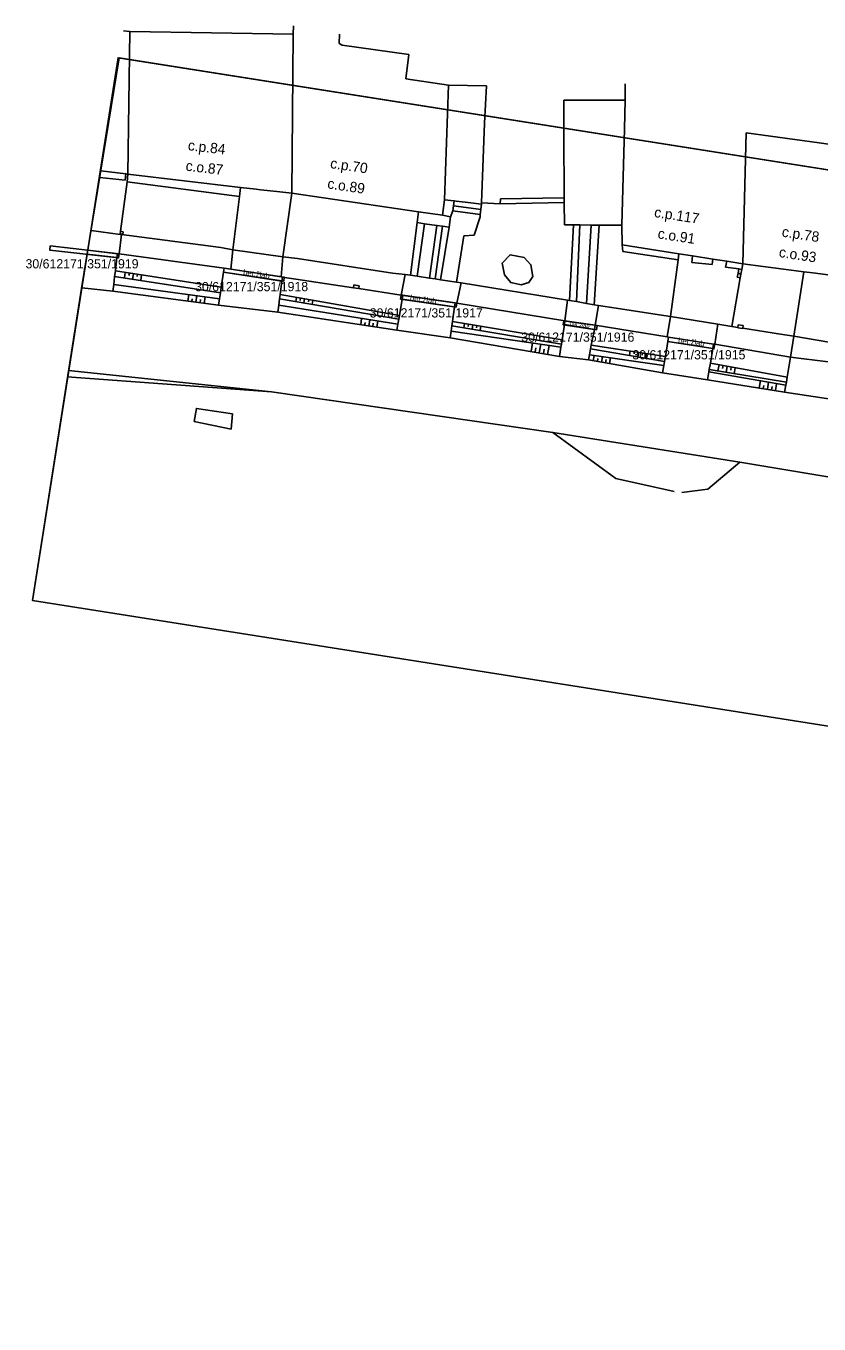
# Model space of a CAD drawing. Extents: x -594451 to -591069, y -1167621 to -1167156.
# Drawn here: x -591409.6 to -591351.9, y -1167315.7 to -1167221.2 of the extents above; entities that cross this region are included whole.
import ezdxf

# ---------------------------------------------------------------- set-up
doc = ezdxf.new("R2010")
doc.units = 0
for name, color, linetype in [('MAPA', 7, 'Continuous'), ('Odvodnění plošné', 7, 'Continuous'), ('Žádosti', 7, 'Continuous')]:
    doc.layers.add(name, color=color, linetype=linetype)

msp = doc.modelspace()

# ---------------------------------------------------------------- linework, layer by layer
at = {"layer": 'MAPA'}
for p, q in [((-591402.511, -1167221.552), (-591402.05, -1167221.59)), ((-591390.15, -1167221.78), (-591390.14, -1167221.19)), ((-591386.774, -1167221.776), (-591386.8, -1167222.46)), ((-591365.975, -1167225.398), (-591365.98, -1167226.59)), ((-591404.241, -1167232.214), (-591402.38, -1167232.41)), ((-591402.75, -1167236.37), (-591404.871, -1167236.093)), ((-591405.15, -1167237.814), (-591402.98, -1167238.05)), ((-591405.103, -1167237.523), (-591402.95, -1167237.77)), ((-591405.545, -1167240.245), (-591403.28, -1167240.5)), ((-591391.73, -1167247.83), (-591406.522, -1167246.268)), ((-591406.6, -1167246.745), (-591391.73, -1167247.83))]:
    msp.add_line(p, q, dxfattribs=at)
for points in [[(-591402.05, -1167221.59), (-591402.18, -1167231.98)], [(-591402.05, -1167221.59), (-591390.15, -1167221.78)], [(-591390.15, -1167221.78), (-591390.25, -1167233.37)], [(-591386.8, -1167222.46), (-591386.58, -1167222.6)], [(-591386.58, -1167222.6), (-591381.73, -1167223.27)], [(-591381.73, -1167223.27), (-591381.96, -1167225.03)], [(-591381.96, -1167225.03), (-591378.85, -1167225.49)], [(-591378.85, -1167225.49), (-591379.14, -1167233.84)], [(-591378.85, -1167225.49), (-591376.08, -1167225.55)], [(-591376.08, -1167225.55), (-591376.228, -1167228.268), (-591376.44, -1167234.06), (-591376.44, -1167234.17)], [(-591370.46, -1167226.6), (-591365.98, -1167226.59)], [(-591370.46, -1167226.6), (-591370.45, -1167229.04), (-591370.43, -1167233.71), (-591370.43, -1167234.05)], [(-591365.98, -1167226.59), (-591366.04, -1167228.67)], [(-591366.04, -1167228.67), (-591366.24, -1167235.69)], [(-591357.18, -1167228.96), (-591357.41, -1167238.5)], [(-591349.29, -1167230.06), (-591351.87, -1167229.7), (-591357.18, -1167228.96)], [(-591404.166, -1167231.75), (-591402.33, -1167231.96), (-591402.18, -1167231.98)], [(-591402.38, -1167232.41), (-591402.33, -1167231.96)], [(-591402.18, -1167231.98), (-591402.25, -1167232.54)], [(-591402.18, -1167231.98), (-591393.99, -1167232.94)], [(-591402.25, -1167232.54), (-591402.72, -1167236.14)], [(-591394.07, -1167233.61), (-591402.25, -1167232.54)], [(-591394.07, -1167233.61), (-591393.99, -1167232.94)], [(-591393.99, -1167232.94), (-591392.85, -1167233.07)], [(-591392.85, -1167233.07), (-591392.53, -1167233.11)], [(-591392.53, -1167233.11), (-591391.35, -1167233.24)], [(-591391.35, -1167233.24), (-591390.25, -1167233.37)], [(-591394.54, -1167237.48), (-591394.07, -1167233.61)], [(-591390.9, -1167237.99), (-591390.25, -1167233.37)], [(-591390.25, -1167233.37), (-591381.02, -1167234.72), (-591379.28, -1167234.97)], [(-591379.14, -1167233.84), (-591379.28, -1167234.97)], [(-591378.28, -1167233.94), (-591378.43, -1167233.92), (-591379.14, -1167233.84)], [(-591378.52, -1167234.66), (-591378.43, -1167233.92)], [(-591378.28, -1167233.94), (-591377.42, -1167234.05)], [(-591376.44, -1167234.17), (-591377.42, -1167234.05)], [(-591376.55, -1167235.08), (-591376.53, -1167234.91), (-591376.44, -1167234.17)], [(-591375.09, -1167234.13), (-591376.44, -1167234.06)], [(-591375.09, -1167234.13), (-591375.06, -1167233.78)], [(-591375.09, -1167234.13), (-591370.43, -1167234.05)], [(-591370.43, -1167233.71), (-591375.06, -1167233.78)], [(-591370.41, -1167235.68), (-591370.43, -1167234.05)], [(-591381.61, -1167239.34), (-591381.14, -1167235.49), (-591381.02, -1167234.72)], [(-591379.42, -1167239.67), (-591378.81, -1167235.83), (-591378.69, -1167235.08)], [(-591378.69, -1167235.08), (-591379.28, -1167234.97)], [(-591378.69, -1167235.08), (-591378.52, -1167234.66)], [(-591378.52, -1167234.66), (-591376.53, -1167234.91)], [(-591378.48, -1167234.29), (-591376.48, -1167234.55)], [(-591376.99, -1167236.43), (-591376.55, -1167235.08)], [(-591402.72, -1167236.14), (-591402.74, -1167236.32)], [(-591402.72, -1167236.14), (-591402.52, -1167236.17)], [(-591381.14, -1167235.49), (-591380.6, -1167235.6)], [(-591381.13, -1167239.41), (-591380.6, -1167235.6), (-591379.69, -1167235.71), (-591380.23, -1167239.55)], [(-591379.81, -1167239.61), (-591379.28, -1167235.77)], [(-591379.69, -1167235.71), (-591379.28, -1167235.77)], [(-591379.28, -1167235.77), (-591378.81, -1167235.83)], [(-591370.41, -1167235.68), (-591369.93, -1167235.68)], [(-591369.74, -1167235.68), (-591370.04, -1167241.17)], [(-591369.93, -1167235.68), (-591369.74, -1167235.68), (-591369.29, -1167235.68), (-591368.47, -1167235.69), (-591367.88, -1167235.69), (-591367.5, -1167235.69)], [(-591369.29, -1167235.68), (-591369.52, -1167241.26)], [(-591368.8, -1167241.39), (-591368.47, -1167235.69)], [(-591367.88, -1167235.69), (-591368.24, -1167241.49)], [(-591367.5, -1167235.69), (-591366.24, -1167235.69)], [(-591366.21, -1167237.13), (-591366.24, -1167235.69)], [(-591402.83, -1167237.78), (-591402.65, -1167236.38)], [(-591402.74, -1167236.32), (-591402.75, -1167236.37)], [(-591395.41, -1167237.33), (-591402.65, -1167236.38), (-591402.75, -1167236.37)], [(-591402.74, -1167236.32), (-591402.56, -1167236.36)], [(-591402.52, -1167236.17), (-591402.56, -1167236.36)], [(-591378.27, -1167239.85), (-591377.72, -1167236.48)], [(-591377.72, -1167236.48), (-591376.99, -1167236.43)], [(-591403.28, -1167240.5), (-591403.22, -1167240.01), (-591403.15, -1167239.43), (-591403.1, -1167239.03), (-591402.98, -1167238.05), (-591402.95, -1167237.77)], [(-591402.95, -1167237.77), (-591402.83, -1167237.78)], [(-591402.83, -1167237.78), (-591395.18, -1167238.83)], [(-591394.54, -1167237.48), (-591395.41, -1167237.33)], [(-591394.54, -1167237.48), (-591394.7, -1167238.9)], [(-591390.9, -1167237.99), (-591394.54, -1167237.48)], [(-591390.9, -1167237.99), (-591391.04, -1167239.45)], [(-591389.85, -1167238.12), (-591390.9, -1167237.99)], [(-591373.34, -1167238.04), (-591372.85, -1167238.58), (-591372.7, -1167239.44), (-591373.01, -1167239.88), (-591373.55, -1167240.04), (-591374.32, -1167239.87), (-591374.78, -1167239.31), (-591374.93, -1167238.46), (-591374.36, -1167237.85), (-591373.34, -1167238.04)], [(-591366.21, -1167237.13), (-591362.08, -1167237.77)], [(-591366.15, -1167237.62), (-591366.21, -1167237.13)], [(-591362.13, -1167238.21), (-591366.15, -1167237.62)], [(-591362.08, -1167237.77), (-591362.13, -1167238.21)], [(-591362.08, -1167237.77), (-591361.08, -1167237.93)], [(-591361.08, -1167237.93), (-591361.14, -1167238.42)], [(-591361.08, -1167237.93), (-591359.61, -1167238.16)], [(-591395.59, -1167241.53), (-591395.52, -1167241.05), (-591395.45, -1167240.61), (-591395.39, -1167240.2), (-591395.22, -1167239.12), (-591395.18, -1167238.83)], [(-591395.18, -1167238.83), (-591394.7, -1167238.9)], [(-591394.7, -1167238.9), (-591391.04, -1167239.45)], [(-591382.92, -1167239.18), (-591389.85, -1167238.12)], [(-591362.69, -1167242.35), (-591362.13, -1167238.21)], [(-591361.14, -1167238.42), (-591359.65, -1167238.56)], [(-591359.65, -1167238.56), (-591359.61, -1167238.16)], [(-591359.61, -1167238.16), (-591358.59, -1167238.32)], [(-591358.59, -1167238.32), (-591358.67, -1167238.76)], [(-591358.67, -1167238.76), (-591357.7, -1167238.87)], [(-591358.59, -1167238.32), (-591357.41, -1167238.5)], [(-591357.7, -1167238.87), (-591357.77, -1167239.2), (-591357.83, -1167239.47)], [(-591357.5, -1167238.92), (-591357.7, -1167238.87)], [(-591357.5, -1167238.92), (-591357.56, -1167239.25), (-591357.61, -1167239.53)], [(-591357.5, -1167238.92), (-591357.41, -1167238.5)], [(-591357.41, -1167238.5), (-591352.98, -1167239.08), (-591352.32, -1167239.17)], [(-591395.45, -1167240.61), (-591403.15, -1167239.43)], [(-591395.39, -1167240.2), (-591403.1, -1167239.03)], [(-591402.44, -1167239.54), (-591402.38, -1167239.14)], [(-591402.11, -1167239.36), (-591402.08, -1167239.18)], [(-591401.84, -1167239.63), (-591401.79, -1167239.23)], [(-591401.51, -1167239.44), (-591401.49, -1167239.27)], [(-591401.25, -1167239.72), (-591401.19, -1167239.32)], [(-591395.22, -1167239.12), (-591390.97, -1167239.76)], [(-591391.28, -1167242.04), (-591391.21, -1167241.53), (-591391.15, -1167241.05), (-591391.11, -1167240.75), (-591390.97, -1167239.76), (-591390.93, -1167239.47)], [(-591391.04, -1167239.45), (-591390.93, -1167239.47)], [(-591390.93, -1167239.47), (-591385.76, -1167240.25)], [(-591382.01, -1167239.28), (-591382.92, -1167239.18)], [(-591382.29, -1167240.78), (-591382.01, -1167239.28)], [(-591379.42, -1167239.67), (-591379.81, -1167239.61), (-591380.23, -1167239.55), (-591381.13, -1167239.41), (-591381.61, -1167239.34), (-591382.01, -1167239.28)], [(-591379.42, -1167239.67), (-591378.27, -1167239.85)], [(-591378.27, -1167239.85), (-591377.92, -1167239.9), (-591370.18, -1167241.15)], [(-591378.25, -1167241.38), (-591377.92, -1167239.9)], [(-591357.61, -1167239.53), (-591358.23, -1167243.07)], [(-591357.61, -1167239.53), (-591357.83, -1167239.47)], [(-591357.56, -1167239.25), (-591357.77, -1167239.2)], [(-591353.71, -1167243.77), (-591352.98, -1167239.08)], [(-591352.32, -1167239.17), (-591351.04, -1167239.34)], [(-591395.59, -1167241.53), (-591403.28, -1167240.5)], [(-591403.22, -1167240.01), (-591395.52, -1167241.05)], [(-591397.76, -1167240.74), (-591397.82, -1167241.23)], [(-591397.16, -1167240.82), (-591397.23, -1167241.31)], [(-591382.41, -1167242.26), (-591391.11, -1167240.75)], [(-591385.76, -1167240.25), (-591385.74, -1167240.05)], [(-591385.76, -1167240.25), (-591385.38, -1167240.31)], [(-591385.74, -1167240.05), (-591385.36, -1167240.11)], [(-591385.38, -1167240.31), (-591385.36, -1167240.11)], [(-591385.38, -1167240.31), (-591382.29, -1167240.78)], [(-591382.6, -1167243.34), (-591382.53, -1167242.91), (-591382.46, -1167242.53), (-591382.41, -1167242.26), (-591382.21, -1167241.09), (-591382.16, -1167240.8)], [(-591382.29, -1167240.78), (-591382.16, -1167240.8)], [(-591382.16, -1167240.8), (-591378.37, -1167241.36)], [(-591397.5, -1167241.05), (-591397.52, -1167241.27)], [(-591396.9, -1167241.11), (-591396.93, -1167241.35)], [(-591396.57, -1167240.9), (-591396.63, -1167241.39)], [(-591395.59, -1167241.53), (-591391.28, -1167242.04)], [(-591391.21, -1167241.53), (-591382.53, -1167242.91)], [(-591382.46, -1167242.53), (-591391.15, -1167241.05)], [(-591389.96, -1167241.26), (-591389.91, -1167240.96)], [(-591389.64, -1167241.18), (-591389.61, -1167241.01)], [(-591389.37, -1167241.36), (-591389.32, -1167241.06)], [(-591389.05, -1167241.28), (-591389.02, -1167241.11)], [(-591388.78, -1167241.46), (-591388.73, -1167241.17)], [(-591382.21, -1167241.09), (-591378.41, -1167241.64)], [(-591378.37, -1167241.36), (-591378.41, -1167241.64), (-591378.56, -1167242.7), (-591378.61, -1167243.02), (-591378.66, -1167243.4), (-591378.73, -1167243.9)], [(-591378.37, -1167241.36), (-591378.25, -1167241.38)], [(-591378.25, -1167241.38), (-591370.37, -1167242.66)], [(-591370.37, -1167242.66), (-591370.18, -1167241.15)], [(-591367.93, -1167241.54), (-591368.24, -1167241.49), (-591368.8, -1167241.39), (-591369.52, -1167241.26), (-591370.04, -1167241.17), (-591370.18, -1167241.15)], [(-591367.93, -1167241.54), (-591368.17, -1167242.98)], [(-591366.64, -1167241.73), (-591367.93, -1167241.54)], [(-591363.66, -1167242.21), (-591366.64, -1167241.73)], [(-591382.6, -1167243.34), (-591391.28, -1167242.04)], [(-591385.18, -1167242.49), (-591385.24, -1167242.95)], [(-591384.92, -1167242.77), (-591384.95, -1167242.99)], [(-591384.58, -1167242.58), (-591384.65, -1167243.04)], [(-591383.99, -1167242.67), (-591384.06, -1167243.12)], [(-591378.56, -1167242.7), (-591370.58, -1167244.04)], [(-591370.76, -1167245.25), (-591370.66, -1167244.58), (-591370.63, -1167244.37), (-591370.58, -1167244.04), (-591370.41, -1167242.93), (-591370.37, -1167242.66)], [(-591370.37, -1167242.66), (-591368.17, -1167242.98)], [(-591362.69, -1167242.35), (-591363.66, -1167242.21)], [(-591362.92, -1167243.83), (-591362.69, -1167242.35)], [(-591359.25, -1167242.91), (-591362.69, -1167242.35)], [(-591384.32, -1167242.84), (-591384.35, -1167243.08)], [(-591382.6, -1167243.34), (-591378.73, -1167243.9)], [(-591370.66, -1167244.58), (-591378.66, -1167243.4)], [(-591370.63, -1167244.37), (-591378.61, -1167243.02)], [(-591377.73, -1167243.17), (-591377.67, -1167242.85)], [(-591377.41, -1167243.07), (-591377.38, -1167242.9)], [(-591377.13, -1167243.27), (-591377.08, -1167242.95)], [(-591376.81, -1167243.17), (-591376.79, -1167243)], [(-591376.54, -1167243.37), (-591376.49, -1167243.05)], [(-591368.23, -1167243.28), (-591370.41, -1167242.93)], [(-591368.65, -1167245.5), (-591368.58, -1167245.13), (-591368.5, -1167244.7), (-591368.45, -1167244.42), (-591368.23, -1167243.28), (-591368.17, -1167242.98)], [(-591368.17, -1167242.98), (-591362.92, -1167243.83)], [(-591359.47, -1167244.37), (-591359.25, -1167242.91)], [(-591358.23, -1167243.07), (-591359.25, -1167242.91)], [(-591357.78, -1167243.14), (-591358.23, -1167243.07)], [(-591357.75, -1167242.94), (-591357.78, -1167243.14), (-591357.78, -1167243.17)], [(-591357.78, -1167243.17), (-591357.43, -1167243.22)], [(-591357.75, -1167242.94), (-591357.39, -1167242.99)], [(-591357.39, -1167242.99), (-591357.43, -1167243.2), (-591357.43, -1167243.22)], [(-591354.68, -1167243.63), (-591357.43, -1167243.2)], [(-591353.71, -1167243.77), (-591354.68, -1167243.63)], [(-591370.76, -1167245.25), (-591378.73, -1167243.9)], [(-591372.72, -1167244.27), (-591372.83, -1167244.89)], [(-591372.48, -1167244.63), (-591372.53, -1167244.94)], [(-591372.13, -1167244.36), (-591372.24, -1167244.99)], [(-591371.53, -1167244.45), (-591371.65, -1167245.1)], [(-591363.06, -1167245.25), (-591368.45, -1167244.42)], [(-591363.26, -1167246.45), (-591363.17, -1167245.91), (-591363.12, -1167245.63), (-591363.06, -1167245.25), (-591362.88, -1167244.16), (-591362.83, -1167243.84)], [(-591362.92, -1167243.83), (-591362.83, -1167243.84)], [(-591359.6, -1167244.67), (-591362.88, -1167244.16)], [(-591362.83, -1167243.84), (-591359.55, -1167244.36)], [(-591359.99, -1167246.95), (-591359.89, -1167246.38), (-591359.86, -1167246.2), (-591359.78, -1167245.75), (-591359.6, -1167244.67), (-591359.55, -1167244.36)], [(-591359.55, -1167244.36), (-591359.47, -1167244.37)], [(-591359.47, -1167244.37), (-591353.94, -1167245.3)], [(-591353.94, -1167245.3), (-591353.71, -1167243.77)], [(-591353.71, -1167243.77), (-591351.01, -1167244.23)], [(-591371.89, -1167244.73), (-591371.94, -1167245.05)], [(-591370.76, -1167245.25), (-591368.65, -1167245.5)], [(-591363.26, -1167246.45), (-591368.65, -1167245.5)], [(-591368.58, -1167245.13), (-591363.17, -1167245.91)], [(-591368.5, -1167244.7), (-591363.12, -1167245.63)], [(-591368.24, -1167245.18), (-591368.31, -1167245.56)], [(-591367.97, -1167245.39), (-591368.01, -1167245.61)], [(-591367.64, -1167245.27), (-591367.71, -1167245.67)], [(-591367.38, -1167245.47), (-591367.42, -1167245.72)], [(-591367.05, -1167245.35), (-591367.12, -1167245.77)], [(-591365.66, -1167245.19), (-591365.61, -1167244.85)], [(-591365.34, -1167245.07), (-591365.32, -1167244.9)], [(-591365.07, -1167245.3), (-591365.02, -1167244.94)], [(-591364.75, -1167245.16), (-591364.72, -1167244.99)], [(-591364.48, -1167245.4), (-591364.43, -1167245.04)], [(-591354.38, -1167247.85), (-591354.29, -1167247.35), (-591354.25, -1167247.13), (-591354.19, -1167246.77), (-591353.94, -1167245.3)], [(-591353.94, -1167245.3), (-591351.21, -1167245.65)], [(-591363.26, -1167246.45), (-591359.99, -1167246.95)], [(-591354.29, -1167247.35), (-591359.89, -1167246.38)], [(-591354.25, -1167247.13), (-591359.86, -1167246.2)], [(-591359.78, -1167245.75), (-591354.19, -1167246.77)], [(-591359.23, -1167246.31), (-591359.15, -1167245.86)], [(-591358.9, -1167246.14), (-591358.86, -1167245.92)], [(-591358.64, -1167246.41), (-591358.56, -1167245.97)], [(-591358.3, -1167246.24), (-591358.27, -1167246.02)], [(-591358.05, -1167246.51), (-591357.97, -1167246.08)], [(-591354.38, -1167247.85), (-591359.99, -1167246.95)], [(-591356.14, -1167247.03), (-591356.22, -1167247.54)], [(-591355.89, -1167247.37), (-591355.93, -1167247.59)], [(-591355.55, -1167247.13), (-591355.63, -1167247.64)], [(-591355.29, -1167247.45), (-591355.33, -1167247.69)], [(-591354.96, -1167247.24), (-591355.04, -1167247.74)], [(-591391.73, -1167247.83), (-591371.26, -1167250.79), (-591357.63, -1167252.95)], [(-591354.38, -1167247.85), (-591350.69, -1167248.41)], [(-591397.37, -1167249.99), (-591397.2, -1167249.04), (-591394.56, -1167249.44), (-591394.68, -1167250.54)], [(-591397.37, -1167249.99), (-591394.68, -1167250.54)], [(-591362.43, -1167255.09), (-591366.67, -1167254.14), (-591371.26, -1167250.79)], [(-591357.63, -1167252.95), (-591359.97, -1167254.91), (-591361.85, -1167255.17)], [(-591357.63, -1167252.95), (-591321.23, -1167259.02), (-591254.866, -1167269.682), (-591254.389, -1167269.757), (-591238.78, -1167272.23)]]:
    msp.add_lwpolyline(points, dxfattribs=at)
at = {"layer": 'Odvodnění plošné'}
for points in [[(-591407.84, -1167237.21), (-591402.83, -1167237.78), (-591402.87, -1167238.08), (-591407.88, -1167237.51)], [(-591395.18, -1167238.83), (-591395.22, -1167239.12), (-591390.84, -1167239.78), (-591390.8, -1167239.49)], [(-591382.29, -1167240.78), (-591382.34, -1167241.07), (-591378.29, -1167241.66), (-591378.25, -1167241.38)], [(-591370.45, -1167242.65), (-591368.02, -1167243), (-591368.08, -1167243.32), (-591370.5, -1167242.94)], [(-591362.83, -1167243.84), (-591359.55, -1167244.36), (-591359.47, -1167244.37), (-591359.52, -1167244.7), (-591359.6, -1167244.67), (-591362.88, -1167244.16)]]:
    msp.add_lwpolyline(points, close=True, dxfattribs=at)
at = {"layer": 'Žádosti'}
for points in [[(-591075.541, -1167315.702), (-591409.141, -1167263.011), (-591402.9, -1167223.501), (-591277.812, -1167243.258), (-591238.702, -1167227.393), (-591201.747, -1167234.05), (-591163.587, -1167259.868), (-591069.3, -1167276.192)], [(-591402.829, -1167223.512), (-591405.554, -1167240.302), (-591409.141, -1167263.011), (-591075.541, -1167315.702), (-591069.3, -1167276.192), (-591163.587, -1167259.868), (-591201.747, -1167234.05), (-591238.702, -1167227.393), (-591277.812, -1167243.258)]]:
    msp.add_lwpolyline(points, close=True, dxfattribs=at)

# ---------------------------------------------------------------- texts
at = {"layer": 'MAPA'}
for s, height, rotation, p in [('c.p.84', 0.75, 353.28079, (-591397.848, -1167230.229)), ('c.o.87', 0.75, 353.28079, (-591398.007, -1167231.721)), ('c.p.70', 0.75, 351.59927, (-591387.493, -1167231.536)), ('c.o.89', 0.75, 351.59927, (-591387.7, -1167233.012)), ('c.p.117', 0.75, 351.25166, (-591363.907, -1167235.094)), ('c.o.91', 0.75, 351.25166, (-591363.653, -1167236.65)), ('c.p.78', 0.75, 351.34967, (-591354.615, -1167236.521)), ('c.o.93', 0.75, 351.34967, (-591354.83, -1167238.003)), ('bet.žlab', 0.4, 351, (-591393.81, -1167239.3)), ('bet.žlab', 0.4, 352, (-591381.67, -1167241.16)), ('bet.žlab', 0.3, 352, (-591370.03, -1167242.98)), ('bet.žlab', 0.4, 352, (-591362.15, -1167244.26))]:
    msp.add_text(s, height=height, rotation=rotation, dxfattribs=at).set_placement(p)
at = {"layer": 'Odvodnění plošné'}
for s, p in [('30/612171/351/1919', (-591409.641, -1167238.841)), ('30/612171/351/1918', (-591397.296, -1167240.501)), ('30/612171/351/1917', (-591384.581, -1167242.416)), ('30/612171/351/1916', (-591373.546, -1167244.181)), ('30/612171/351/1915', (-591365.461, -1167245.466))]:
    msp.add_text(s, height=0.67082, dxfattribs=at).set_placement(p)

doc.saveas('drawing.dxf')
